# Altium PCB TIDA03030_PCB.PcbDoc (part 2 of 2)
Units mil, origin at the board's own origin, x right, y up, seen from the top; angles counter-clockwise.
Board outline 2230 x 2185 mil, 4 copper layers (Top Layer, Power, Gnd, Bottom Layer), stack 59.6 mil thick; 88 components, 48 nets, 250 pads, 119 vias.
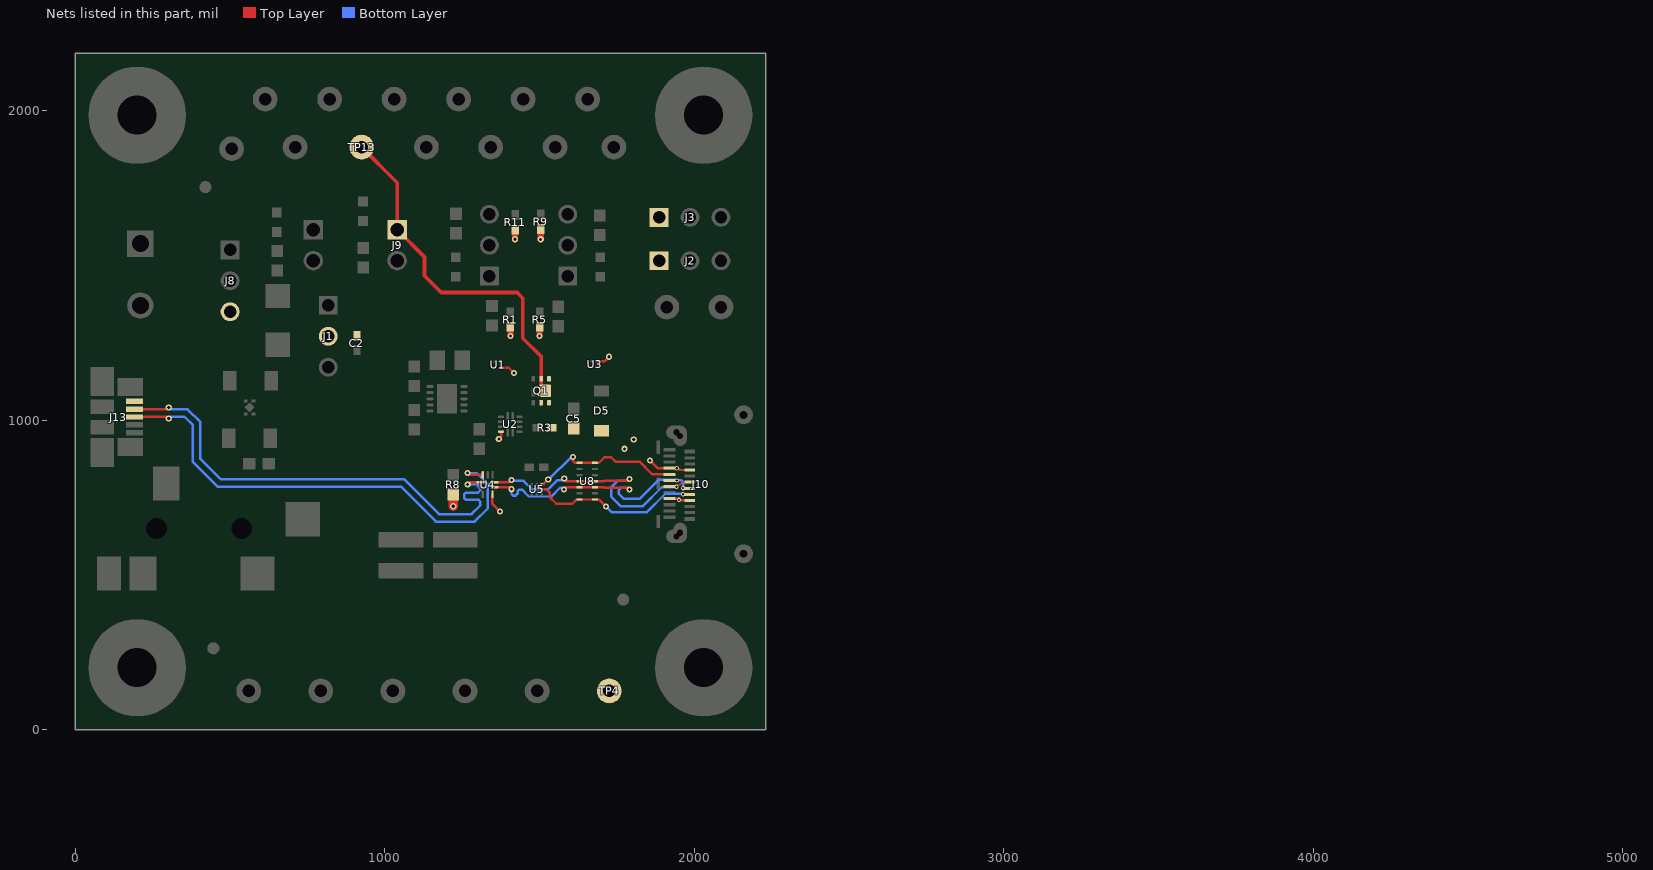
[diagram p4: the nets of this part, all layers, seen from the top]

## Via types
v1: diameter 20, hole 10, Top Layer to Bottom Layer, 108 vias
v2: diameter 14, hole 7, Top Layer to Bottom Layer, 7 vias
v3: diameter 19.68, hole 7.87, Top Layer to Bottom Layer, 4 vias

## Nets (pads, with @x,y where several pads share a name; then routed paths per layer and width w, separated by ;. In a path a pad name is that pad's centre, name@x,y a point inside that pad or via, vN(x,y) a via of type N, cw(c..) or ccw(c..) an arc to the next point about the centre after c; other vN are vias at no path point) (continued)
USB_C_D+: J10.A6 J10.B6 U4.7 U8.4 U8.11 | length 871.2
  Top Layer w6: v2(1942.44,784.84) 1948.75,791.16 1952.85,791.16 1961.09,799.4 J10.B6@1984.56,799.4
  Top Layer w8: U4.7@1355.62,799.44 1401.66,799.44 v1(1409.12,806.9) ; v1(1579.55,811.35) 1579.55,808.11 1585.09,802.57 U8.11@1629.39,802.57 U8.4@1678.61,802.57 1708.86,802.57 1711.02,804.72 1785.59,804.72 v1(1790.09,809.22)
  Bottom Layer w8: v1(1409.12,806.9) 1412.13,803.89 1448.23,803.89 1474.92,777.2 1528.19,777.2 1556.39,805.4 1573.61,805.4 v1(1579.55,811.35) ; v1(1790.09,809.22) 1785.59,804.72 1752.94,804.72 1731.07,782.85 1731.07,752.87 1762.74,721.2 1832.88,721.2 1894.65,782.98 1940.57,782.98 v2(1942.44,784.84)
USB_C_D-: J10.A7 J10.B7 U4.6 U8.3 U8.12 | length 813.1
  Top Layer w8: U4.6@1355.62,783.69 1402.41,783.69 v1(1409.22,776.88) ; v1(1578.92,775.46) 1578.92,777.02 1584.78,782.88 U8.12@1629.39,782.88 U8.3@1678.61,782.88 1708.43,782.88 1710.59,780.72 1785.59,780.72 v1(1790.09,776.22)
  Bottom Layer w8: v1(1409.22,776.88) 1409.22,760.95 1414.07,756.1 1422.74,756.1 1428.94,762.31 1428.94,771.05 1433.15,775.26 1442.93,775.26 1464.98,753.2 1538.13,753.2 1566.33,781.4 1572.98,781.4 v1(1578.92,775.46) ; v1(1790.09,776.22) 1785.59,780.72 1762.88,780.72 1755.07,772.91 1755.07,762.81 1772.68,745.2 1822.94,745.2 1884.71,806.98 1940.96,806.98 v2(1942.83,805.11) 1958.46,805.11 1964.12,799.45 1964.12,780.6 v2(1963.62,780.1)
USB_C_SBU1: J10.A8 U5.A3 U8.7 U8.8 | length 495.6
  Top Layer w8: U5.A3@1506.42,792.95 1513.11,792.95 v1(1528.03,807.87) ; v1(1607.7,881.21) 1607.7,868.62 1614.7,861.62 U8.8@1629.39,861.62 U8.7@1678.61,861.62 1691.19,861.62 1709.57,880.01 1731.25,880.01 1745.46,865.8 1822.35,865.8 1863.16,824.99 J10.A8@1919.6,824.99
  Bottom Layer w8: v1(1528.03,807.87) 1529.21,807.87 1602.55,881.21 v1(1607.7,881.21)
USB_C_SBU2: J10.B8 U5.B3 U8.1 U8.14 | length 532.9
  Top Layer w8: U5.B3@1506.42,777.2 1521.42,777.2 1532.38,766.24 1532.38,751.24 1553.73,729.89 1605.73,729.89 1619.35,743.51 U8.14@1629.39,743.51 U8.1@1678.61,743.51 1692.26,743.51 v1(1714.47,721.3)
  Bottom Layer w8: v1(1714.47,721.3) 1732.9,702.87 1846.78,702.87 1905.94,762.04 1961.55,762.04 v2(1963.24,760.34)
USB_C_VBUS: C5.1 D5.1 J9.1 J10.A4 J10.A9 J10.B4 J10.B9 Q1.1 Q1.2 Q1.5 Q1.6 Q1.8 R3.2 TP13.1 | length 1384.6
  Top Layer w8: v1@1856.56,869.41 1881.3,844.67 J10.A9@1919.6,844.67 1947.46,844.67 1953.37,838.77 J10.B4@1984.56,838.77 ; J10.A4@1919.6,746.25 1946.48,746.25 v2(1950.48,742.24) 1952.39,740.34 J10.B9@1984.56,740.34
  Top Layer w12: TP13.1@925,1882 1039.82,1767.18 J9.1@1039.82,1615 1128,1526.82 1128,1466 1182,1412 1427.64,1412 1445.63,1394.01 1445.63,1264.55 1505.78,1204.41 1505.78,1107.02 Q1.8@1517.8,1095
  other v1: 1856.52,869.41 1774.03,907.16 1804.2,937.14
  other v2: 1943.14,844.3
USB_D+: J13.3 U4.10 | length 1583.2
  Top Layer w8: J13.3@191.61,1010 222.78,1010 223.57,1010.8 295.88,1010.8 v1(301.88,1004.8) ; v1(1267.51,829.05) 1273.5,823.06 U4.10@1316.25,823.06
  Bottom Layer w8: v1(301.88,1004.8) 307.88,1010.8 352.68,1010.8 379.85,983.63 379.85,864.68 459.41,785.12 1052.06,785.12 1164.84,672.34 1290,672.34 1332.38,714.72 1332.38,793.63 1296.96,829.05 v1(1267.51,829.05)
USB_D-: J13.2 U4.1 | length 1583.1
  Top Layer w8: J13.2@191.61,1035.59 222.78,1035.59 223.57,1034.8 295.88,1034.8 v1(301.88,1040.8) ; v1(1267.64,792.08) 1275,799.44 U4.1@1310.35,799.44
  Bottom Layer w8: v1(301.88,1040.8) 307.88,1034.8 362.63,1034.8 403.85,993.57 403.85,874.63 469.35,809.12 1062,809.12 1174.78,696.34 1280.06,696.34 1308.38,724.66 1308.38,736.62 1303,742 1261.81,742 1256,747.81 1256,760.16 1261.84,766 1301,766 1308.38,773.38 1308.38,783.69 1299.99,792.08 v1(1267.64,792.08)
USB_VBUS: J8.3 J13.1
VDD: C2.1 J1.2 J2.1 J3.1 R1.1 R5.1 R8.1 R9.2 R11.2 TP4.1 U1.A2 U2.12 U3.A2 U4.5 | length 345.9
  Top Layer w8: U4.5@1347.75,760.07 1347.75,729.25 v1(1372,705) ; v1(1368.2,939.11) 1375.47,946.38 U2.12@1375.47,962.94 ; U1.A2@1374.84,1169.16 1400.3,1169.16 v1(1417.22,1152.24) ; U3.A2@1687.84,1190.84 1710.79,1190.84 v1(1724.56,1204.61)
  Top Layer w12: v1(1503.55,1584.02) v1@1504,1584.47
  Top Layer w20: v1(1405.5,1271.49) R1.1@1405.5,1301.38 ; v1(1421,1584.28) R11.2@1421,1615.38 ; v1(1500,1271.49) R5.1@1500,1301.38 ; v1@1504,1584.47 R9.2@1504,1617.38
  Top Layer w30: v1(1221,721.76) R8.1@1221,759.5
pads on no net: FID1.1 FID2.1 FID3.1 H1.1 H2.1 H3.1 H4.1 H7.0 H8.0 H9.0 H10.0 H11.0 H12.0 J10.A2 J10.A3 J10.A10 J10.A11 J10.B2 J10.B3 J10.B10 J10.B11 J12.5 J12.MH1 J12.MH2 J13.4 U2.1P U2.2P U2.7P U2.8P

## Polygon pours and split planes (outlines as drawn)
GND on Gnd "Power-No Net" (solid, pour order 23): 14,2161 27,2161 27,18 483,18 2209,18 2209,424 2209,2161 2099,2161
5V0 on Power "Power-No Net" (solid, pour order 13): 1806.26,2169.8 17.04,2169.8 17.04,1813.67 17.04,14.29 920.88,14.29 920.88,301.08 704.25,301.08 704.26,1020.77 626.31,1020.77 564.46,1020.77 564.46,1120.68 564.48,1184.93 564.48,1236.14 617.03,1236.14 761.2,1236.14 761.2,1283.62 761.2,1334.26 1011.14,1334.26 1011.14,1017.38 1062.81,1017.38 1132.53,1017.38 1132.53,1334.26 1397.1,1334.26 1397.11,1627.95 1806.26,1627.95
VDD on Power "Power-No Net" (solid, pour order 11): 775.46,1322.52 775.46,1323.1 1000.97,1323.1 1000.97,1031.92 1000.97,1008.96 1143.18,1008.96 1143.18,1322.52 1407.74,1322.52 1407.74,1423.09 1407.74,1616.34 1755.36,1616.34 1824.56,1616.34 1824.56,2169.63 2212.45,2169.63 2212.45,1575.23 2212.45,14.41 2108.07,14.41 1652.84,14.41 1652.84,149.76 1652.84,605.79 1194.86,605.78 1194.86,733.36 1562.45,733.36 1562.45,756.33 1562.45,984.71 1380.23,984.71 1380.23,897.12 876.99,897.12 876.99,1226.73 803.33,1226.73 775.17,1226.73 775.17,1318.05
3V3 on Power "Power-No Net" (solid, pour order 9): 864.86,886.97 864.86,1215.81 747.67,1215.81 580.74,1215.81 580.74,1038.03 593.59,1038.03 716.14,1038.03 716.14,827.77 716.14,314.93 937.8,314.93 937.8,14.36 1636.47,14.36 1636.47,105.65 1636.47,593.44 1521.27,593.44 1182.74,593.44 1182.74,744.93 1546.66,744.93 1546.66,973.51 1393.07,973.51 1393.07,886.97
GND on Bottom Layer "Power-No Net" (solid, pour order 7): 16.97,2154.82 16.98,2154.82 16.98,1726.07 16.98,16.53 1376.94,16.53 2210.03,16.53 2210.03,293.64 2210.03,2153.84 2050.3,2153.84

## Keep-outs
Keep-Out Layer:
  text "Keep - Out Layer" at -1418,-1898.49 h60

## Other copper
Top Layer:
  region net GND: 1990.59,686.27 1945.23,686.27 1937.42,694.08 1881.11,694.08 1878.38,696.81 1831.48,696.81 1819.8,685.13 1819.8,602.96 1898.1,524.66 2159.25,524.66 2182.11,547.52 2181.71,547.92 2181.71,582.08 2163.89,599.91 2056.54,599.91 2040.87,584.24 1989.18,584.24 1966.65,606.77 1966.65,649.17 1991.12,673.64 1991.12,685.75
  region net GND: 1590.09,1083.88 1630.73,1124.52 2157.88,1124.52 2193.98,1088.41 2193.98,1004.96 2172.41,983.39 2123.81,983.39 2076.56,1030.64 2026.58,1030.64 2001.94,1006 2001.94,892.91 1967.43,892.74 1961.45,898.72 1893.66,898.72 1889.99,895.06 1889.99,890.77 1888.13,888.9 1879.62,888.9 1876.42,892.1 1876.42,929.57 1767.63,1038.36 1729.97,1076.03 1656.26,1076.03 1629.89,1049.66 1629.89,1016.6 1590.09,1016.4
  region net USB_C_VBUS: 1724,984 1777.17,984 1819.97,941.2 1819.97,926.16 1787.2,893.39 1767.4,893.39 1718.07,942.72
  region net VDD: 1366.73,968.08 1364.51,965.86 1364.51,954.89 1353.66,944.04 1353.66,930.29 1358.07,925.88 1379.29,925.97 1385.36,932.04 1385.36,965.73 1383.02,968.08
  region net GND: 1497.56,860.04 1497.56,835.45 1485.72,823.61 1485.72,774.87 1487.96,772.63 1494.51,772.63 1495.7,773.82 1495.7,808.2 1523.41,835.91 1531.54,835.91 1531.54,859.96
  region net 5V0: 569.9,1025.02 665.19,1025.02 697.82,992.39 697.82,845.92 677.89,825.99 613.44,825.99 613.44,826.08 604.78,834.74 604.78,906.33 607.61,909.17 607.61,967.74 570.08,1005.26 570.08,1010.88
  region net VDD: 783.95,1295.03 783.95,1244.03 792.65,1235.33 872.87,1235.33 893.83,1256.28 932.97,1256.28 941.68,1265 941.16,1265.53 941.16,1297.56 931.18,1307.54 796.38,1307.54
  region net USB_VBUS: 523.74,1383.68 460.58,1383.68 446.89,1369.98 446.89,1289.97 227.62,1070.7 165.28,1070.7 163.6,1069.03 163.6,1052.56 164.96,1051.2 166.8,1051.2 279.22,1051.2 297.52,1069.49 325.48,1069.49 539.1,1283.11 539.11,1369.44
  region net GND: 48.12,1202.5 30,1220.62 30,1558 85,1613 267,1613 282,1598 282,1542 267,1527 142,1527 114,1499 114,1284 150,1248 214,1248 226.61,1235.39 226.61,1197.73
  region net GND: 1075,1258 1093,1276 1182,1276 1196,1262 1196,1159 1235,1120 1235,967 1159.93,891.93 1067.97,891.93 1056.45,903.45 1056.45,977.83 1068.63,990.1 1074,990.14 1136.14,990.14 1168,1022 1168,1132 1148,1152 1077,1152 1075,1154
  region net NetJ6_1: 1440.68,1106 1310.44,1106 1278.44,1074 1246,1074 1243,1071 1243,1024 1248,1019 1288.43,1019 1337.71,1068.28 1450.41,1068.28 1473.69,1045 1483,1045 1487,1049 1487,1103 1484,1106
  region net NetR1_2: 1327.15,1388.66 1411.03,1388.66 1424.86,1374.84 1424.86,1338.46 1419.26,1332.87 1390.86,1332.87 1375.36,1348.37 1327.04,1348.37 1324.56,1350.85 1324.56,1386.09
  region net NetR5_2: 1540.6,1388.5 1581.68,1388.5 1588.05,1382.12 1588.05,1351.75 1582.86,1346.56 1527.8,1346.56 1514.14,1332.9 1485.54,1332.9 1482.15,1336.29 1482.15,1376.24 1494.07,1388.17
  region net 3V3: 569.9,1057.22 569.83,1086.22 576.36,1092.73 611.23,1092.73 611.23,1158.23 617.27,1164.27 677.73,1164.27 686.08,1155.92 686.08,1084.08 659.22,1057.22
  region net NetJ7_2: 148.32,1419.24 289.24,1419.24 457.34,1587.34 539.72,1587.34 546.03,1581.03 546.03,1520.03 533.17,1507.17 481.17,1507.17 285.21,1311.21 148.32,1311.21
  region net GND: 48.04,1171.27 48.04,798.11 70.83,775.32 195.73,775.32 219.46,799.05 219.46,942.67 219.49,967.96 218.53,968.92 164.53,968.92 162.56,966.95 162.56,948.28 156.24,941.96 126.36,941.96 124.57,943.76 124.57,1069.57 132.82,1077.82 222.88,1077.82 226.61,1081.54 226.61,1197.73 207.05,1217.29 62.95,1217.29 48.12,1202.5
  region net USB_C_VBUS: 1498.83,1148.9 1498.83,1041.17 1523.87,1016.13 1523.87,957.13 1547.22,933.78 1727,933.78 1727,981 1724,984 1638,984 1629,993 1588,993 1569,1012 1569,1144.18 1561.18,1152 1501.93,1152
  region net GND: 566.86,1283 553.94,1270.07 553.94,1214.13 564.06,1204 754.42,1204 754.42,1283
  region net 5V0: 475,1410 539,1410 588,1361 758,1361 779,1340 852,1340 860,1348 860,1422 832,1450 826,1450 601,1450 560,1491 481,1491 463,1473 463,1422
  region net 5V0: 1156,1075 1137,1075 1115,1053 1018.06,1053 1011.14,1046.08 1011.14,1018.42 1016.57,1013 1144,1013 1158,1027 1158,1073
  region net GND: 578.87,1041.26 578.4,1040.78 531.51,1040.78 517.96,1027.24 517.96,909.35 510.88,902.27 470.59,902.27 463.24,909.62 463.24,1154.01 473.52,1164.29 517.23,1164.29 523.6,1157.93 523.6,1092.74 557.22,1092.74 563.07,1086.88 563.07,1041.27
  text "TOP Layer" at -1415,-1905 h60
Gnd:
  text "GND" at -1405,-1905 h60
Power:
  text "POWER" at -1458,-1908 h60
Bottom Layer:
  region net USB_C_VBUS: 1753.5,937.78 1753.5,896.06 1765.9,883.66 1822.45,883.66 1869.6,836.51 1950.27,836.51 1957.27,843.51 1970.85,843.51 1978.83,835.53 1978.83,751.22 1970.94,743.33 1962.78,743.33 1956.55,749.56 1936.15,749.56 1933.51,746.92 1933.51,726.94 1938.27,722.18 1990.78,722.18 2002.16,733.56 2002.15,874.53 1986.11,890.57 1888.21,890.57 1824.9,953.89 1769.61,953.89
  text "BOTTOM Layer" at -1395,-1905 h60

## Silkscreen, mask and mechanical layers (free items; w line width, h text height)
Top Overlay:
  text "TOP Overlay" at -1418,-1898.49 h60
Bottom Overlay:
  text "Bottom Overlay" at -1418,-1898.49 h60
Top Paste:
  text "Top Paste" at -1418,-1898.49 h60
Bottom Paste:
  text "Bottom Paste" at -1418,-1898.49 h60
Top Solder:
  text "Top Solder" at -1418,-1898.49 h60
Bottom Solder:
  text "Bottom Solder" at -1418,-1898.49 h60
Drill Guide:
  text "Drill guide" at -1418,-1898.49 h60
M1 Board Outline:
  lines w3.94: 2215.86,613.37 2230,613.37 2230,601.28 2230.03,601.28 2230.03,0 ; 2215.86,971.64 2230,971.64 ; 2230,0 0,0 0,2185 2230,2185 2230,971.64 ; 2230,971.64 2230,971.64
  text "M1 Board Outline" at -1418,-1898.49 h60
M2 Board Dimensions:
  rectangle: -725,-405 -600,-280
  rectangle: -600,-530 -225,-405
  lines w7: -725,-405 275,-405 ; -600,-530 -600,-280 ; -475,-530 -475,-280 ; -225,-530 -225,-280 ; 25,-530 25,-280 ; -725,-530 275,-530 275,-280 -725,-280 -725,-530
  lines w10: 1061.09,1146.84 1061.16,1213.95 ; 1061.15,938.26 1061.15,999.16 ; 1061.23,743.01 1061.23,696 1102.27,696 ; 1061.23,810.7 1061.23,841.06 ; 1061.23,1046.91 1061.23,1084.58 ; 1109.79,1228 1149.72,1228 ; 1202.93,696 1242.49,696 ; 1230.57,1228 1269.48,1228 ; 1289.04,696 1326.39,696 ; 1342.75,1228 1398.25,1228 ; 1449.93,1228 1473.11,1228 ; 1521.39,1228 1560.18,1228 ; 1606.96,1228 1632.23,1228 ; 1650.45,696 1695.04,696 ; 1687.26,1228 1708.79,1228 ; 1756.48,696 1786,696 1786,721.24 ; 1757.12,1228 1786,1228 1786,1199.38 ; 1786,860.92 1786,896.91 ; 1786,972.04 1786,1019.46
  text "M2 Board Dimension" at -1418,-1898.49 h60
M3 3D STEP Top:
  text ".Layer_Name" at -1418,-1898.49 h60
M4 3D STEP Bottom:
  text ".Layer_Name" at -1418,-1898.49 h60
M5 Assembly Top:
  lines w10: -2287,-1970.17 4313,-1970.17 ; -2287,-1766.83 4315,-1766.83 ; -2287,-1563.5 -2287,-2173.5 1718,-2173.5 4315,-2173.5 4315,-1563.5 -2286.5,-1563.5 -2286.5,-2173.5 -711,-2173.5 ; 178,-2173.5 178,-1563.5 ; 1445,-1766.83 1445,-1563.5 ; 2285,-1766.83 2285,-1563.5 ; 2907,-2180 2907,-1977.17
  text "COMPONENTS MARKED 'DNP' SHOULD NOT BE POPULATED." at -841.5,-1358.5 h60
  text "ASSEMBLY VARIANT:" at -842,-1474 h60
  text ".VariantName" at 194,-1474 h60
  text "PCB VIEWED FROM TOP SIDE" at -2223.5,-1695.67 h60
  text "BOARD #:" at 253,-1695.67 h60
  text ".PRJ_Number" at 798.5,-1695.67 h60
  text "REV:" at 1643,-1695.67 h60
  text ".PCB_Rev" at 1934.5,-1695.67 h60
  text "SVN REV:" at 2481,-1695.67 h60
  text ".VersionControl_RevNumber" at 2987,-1695.67 h60
  text "TID #:" at 253,-1899 h60
  text ".TID" at 798.5,-1899 h60
  text "PLOT NAME =" at -2223.5,-2104.34 h60
  text ".plot_File_Name" at -1418,-2104.34 h60
  text "GENERATED    :" at 255,-2104.34 h60
  text ".Print_Date" at 1124.5,-2104.34 h60
  text ".Print_Time" at 1853.5,-2104.34 h60
  text "TEXAS INSTRUMENTS" at 3118,-2104.34 h60
M6 Assembly Bottom:
  lines w10: -2287.5,-1767.33 4314.5,-1767.33 ; -2285.5,-1970.67 4314.5,-1970.67 ; -879.5,-2180.5 -879.5,-1977.67 ; -257.5,-1767.33 -257.5,-1564 ; 582.5,-1767.33 582.5,-1564 ; 1849.5,-2174 1849.5,-1564 ; 2738.5,-2174 4314,-2174 4314,-1564 -2287.5,-1564 -2287.5,-2174 309.5,-2174 4314.5,-2174 4314.5,-1564
  text "COMPONENTS MARKED 'DNP' SHOULD NOT BE POPULATED." at 4107,-1358 h60
  text ".VariantName" at 3063,-1474 h60
  text "ASSEMBLY VARIANT:" at 4102,-1474 h60
  text ".VersionControl_RevNumber" at -959.5,-1696.17 h60
  text "SVN REV:" at -453.5,-1696.17 h60
  text ".PCB_Rev" at 93,-1696.17 h60
  text "REV:" at 384.5,-1696.17 h60
  text ".PRJ_Number" at 1229,-1696.17 h60
  text "BOARD #:" at 1774.5,-1696.17 h60
  text "PCB VIEWED FROM BOTTOM SIDE" at 4251,-1696.17 h60
  text ".TID" at 1229,-1899.5 h60
  text "TID #:" at 1774.5,-1899.5 h60
  text "TEXAS INSTRUMENTS" at -1090.5,-2104.84 h60
  text ".Print_Time" at 174,-2104.84 h60
  text ".Print_Date" at 903,-2104.84 h60
  text "GENERATED    :" at 1772.5,-2104.84 h60
  text ".plot_File_Name" at 3445.5,-2104.84 h60
  text "PLOT NAME =" at 4251,-2104.84 h60
M9 Title Sheet:
  drawing of 57 lines, arcs and shapes, not listed
  text "1" at -1255.16,6996.5 h70
  text "2" at 1240.5,6996.5 h70
  text "3" at 3729.84,6996.5 h70
  text "4" at 6236.51,6996.5 h70
  text "5" at 8735.5,6996.5 h70
  text "6" at 11240.5,6996.5 h70
  text "A" at -2411.5,5853.5 h70
  text "A" at 12388.5,5853.5 h70
  text "B" at -2411.5,3473.5 h70
  text "B" at 12388.5,3473.5 h70
  text "C" at -2411.5,1098.5 h70
  text "C" at 12388.5,1098.5 h70
  text "PROJECT TITLE:" at 9348.5,-762.5 h45
  text "TIDA03030" at 9398.5,-895.83 h70
  text "DESIGNED FOR:" at 9348.5,-1063.5 h45
  text "TI_TIDA03030" at 9398.5,-1203.5 h70
  text "D" at -2411.5,-1271.5 h70
  text "D" at 12388.5,-1271.5 h70
  text "FILE NAME:" at 9348.5,-1363.5 h45
  text "TIDA03030_PCB_PcbDoc" at 9398.5,-1483.5 h70
  text "Texas Instruments (TI) and/or its licensors do not warrant the accuracy or completeness of this specification" at 4379,-1645.34 h45
  text "ENGINEER:" at 9348.5,-1653.5 h45
  text "LAYOUT BY:" at 10853.5,-1653.5 h45
  text "or any information contained therein. TI and/or its licensors do not warrant that this design will meet" at 4334.01,-1758 h45
  text "ANDY" at 9398.5,-1808.49 h70
  text "PACTRONINC" at 10904,-1808.49 h70
  text "the specifications, will be suitable for your application or fit for any particular purpose, or will operate in" at 4334.01,-1870.67 h45
  text "M9  Title Sheet" at -1418,-1898.49 h60
  text "ALTIUM DESIGNER VERSION:" at 10853.5,-1963.5 h45
  text "an implementation. TI and/or its licensors do not warrant that the design is production worthy. You should" at 4334.01,-1983.33 h45
  text "completely validate and test your design implementation to confirm the system functionality for your application." at 4379,-2096 h45
  text "Scale : 1.00" at 9398.5,-2096.83 h70
  text "14.3.14.34663" at 10904,-2096.83 h70
  text "1" at -1255.16,-2303.5 h70
  text "2" at 1240.5,-2303.5 h70
  text "3" at 3729.84,-2303.5 h70
  text "4" at 6236.51,-2303.5 h70
  text "5" at 8735.5,-2303.5 h70
  text "6" at 11240.5,-2303.5 h70
M10 Fab Notes:
  drawing of 173 lines, arcs and shapes, not listed
  text "DESIGN INFORMATION" at 10383.02,5161 h60
  text "MIN. TRACK WIDTH:" at 9738.46,4981 h60
  text "6" at 10834.7,4981 h60
  text "MIL" at 10989.46,4981 h60
  text "5" at 10835,4850 h60
  text "MIN. CLEARANCE:" at 9738.46,4849 h60
  text "MIL" at 10989.46,4849 h60
  text "MIN. VIA PAD SIZE:" at 9738.46,4717 h60
  text "14" at 10804.71,4717 h60
  text "MIL" at 10989.46,4717 h60
  text "0.05mm (2MIL)" at 10433.46,4575.29 h60
  text "MINIMUM ANNULAR RING" at 9409.23,4571 h60
  text "EXTERNAL" at 11141.46,4571 h60
  text "PER" at 9609.23,4453 h60
  text "IPC-D-275 CLASS 2 LEVEL C" at 9829.23,4453 h60
  text "MIL, HOLES" at 11317.46,4340.71 h60
  text "+/-" at 10925,4340 h60
  text "+/-" at 11779,4340 h60
  text "REGISTRATION TOLERANCES:" at 9409.23,4335 h60
  text "METAL" at 10609,4335 h60
  text "5" at 11185.2,4335 h60
  text "3" at 12018.2,4335 h60
  text "MIL" at 12134.46,4335 h60
  text "+/-" at 11779,4222 h60
  text "HOLE SIZE TOLERANCE (UNLESS OTHERWISE SPECIFIED):" at 9409.23,4217 h60
  text "3" at 12018.2,4217 h60
  text "MIL" at 12134.46,4217 h60
  text "MATERIAL:" at 9334.46,4007.54 h60
  text "FR-4 High Tg" at 10320.9,3867.21 h60
  text "FR-408" at 9755.46,3858.64 h60
  text "OTHER" at 11243.46,3858.64 h60
  text "X" at 10166,3855 h60
  text "62MIL (1.6mm) +/-10%" at 10075.56,3695.92 h60
  text "THICKNESS:" at 9409.23,3691.64 h60
  text "X" at 9947.4,3691.64 h60
  text "OTHER" at 11360.46,3691.64 h60
  text "TOLERANCE:" at 9409.23,3533.64 h60
  text "X" at 10248.53,3533.64 h60
  text "ANSI IPC-6012 TYPE 3 CLASS 2" at 10435.48,3533.64 h60
  text "OTHER +/-" at 10435.46,3377.64 h60
  text "BOW & TWIST:" at 9409.23,3220.64 h60
  text "X" at 10248.53,3220.64 h60
  text "ANSI IPC-6012 TYPE 3 CLASS 2" at 10435.48,3220.64 h60
  text "OTHER +/-" at 10435.46,3062.13 h60
  text "DRILLING:" at 9334.46,2923.64 h60
  text "REFERENCE:" at 9409.23,2806.64 h60
  text "X" at 10057.46,2806.64 h60
  text "AS SHOWN" at 10244.46,2806.64 h60
  text "X" at 10958.46,2806.64 h60
  text "NC_DRILL FILES" at 11095.46,2806.64 h60
  text "PTH COPPER THICKNESS:" at 9409.23,2648.64 h60
  text "X" at 10539.46,2648.64 h60
  text "20-30 um" at 10676.46,2648.64 h60
  text "OTHER" at 11393.46,2648.64 h60
  text "BOARD FINISH:" at 9334.46,2489.64 h60
  text "SILKSCREEN:" at 9489.68,2371.64 h60
  text "X" at 10438.46,2371.64 h60
  text "TOP" at 10564.46,2371.64 h60
  text "X" at 10948.46,2371.64 h60
  text "BOTTOM" at 11075.46,2371.64 h60
  text "SILKSCREEN COLOR:" at 9489.68,2204.64 h60
  text "X" at 10437.42,2204.64 h60
  text "WHITE" at 10564.46,2204.64 h60
  text "OTHER" at 11075.46,2204.64 h60
  text "X" at 10568.42,2045.44 h60
  text "GREEN" at 10695.46,2045.44 h60
  text "OTHER" at 11313.46,2045.44 h60
  text "SOLDER RESIST COLOR:" at 9489.68,2034.64 h60
  text "MATTE" at 10695.46,1875.44 h60
  text "SEMI-GLOSS" at 11313,1874.8 h60
  text "IMMERSION GOLD (ENIG)" at 10395.46,1686.92 h60
  text "ENEPIG" at 11733,1683.64 h60
  text "SURFACE FINISH:" at 9334.46,1682.64 h60
  text "X" at 10208.51,1682.64 h60
  text "IMM. TIN/SILVER OR EQUIV" at 9664,1525.64 h60
  text "OTHER" at 11095.46,1525.64 h60
  text "ARRAY/PANEL:" at 9334.46,1346.64 h60
  text "CUT AND TRIM PER M1 BOARD OUTLINE" at 10395.46,1342.35 h60
  text "N.C. ROUTE" at 10395.46,1190.64 h60
  text "V. SCORE" at 11261.46,1190.64 h60
  text "CERTIFICATION:" at 9334.46,1053.64 h60
  text "MATERIALS AND WORKMANSHIP FOR ALL PCBS" at 10059.46,1053.64 h60
  text "TO MEET OR EXCEED THE REQUIREMENTS OF:" at 10059.46,955.64 h60
  text "X" at 9685.96,819.13 h60
  text "ANSI IPC-A-600F CLASS ->" at 9824.96,819.13 h60
  text "X" at 11464.02,819.13 h60
  text "2" at 11582.96,819.14 h60
  text "1" at 11267.96,817.64 h60
  text "3" at 11936.96,817.64 h60
  text "X" at 10500.02,659.64 h60
  text "RoHS" at 10636.96,659.64 h60
  text "OTHER" at 11281.36,659.64 h60
  text "PER ORDER" at 11678.42,659.64 h60
  text "Note:" at 2949.6,582.97 h100
  text "ALL BOARDS MUST MEET OR EXCEED UL94-V0 REQUIREMENTS." at 9362,494 h60
  text "All 8 mil traces with 16mil air gap on  top and bottom  layer need to be controlled impedance of 100ohms" at 2944.31,440.43 h100
  text "PCB MUST BEAR THE UL94V-0 UL REGISTERED MATERIAL ID NUMBER" at 9362,374 h60
  text "ADDITIONAL REQUIREMENTS:" at 9334.46,200.64 h60
  text "MICROSECTION:" at 9409.23,85.64 h60
  text "YES" at 10314.96,85.64 h60
  text "REQUIRED" at 11176.46,-70.51 h60
  text "BARE BOARD ELEC. TEST:" at 9409.23,-73.36 h60
  text "NONE" at 10714.96,-73.36 h60
  text "X" at 11049.46,-73.36 h60
  text "PER ORDER" at 11768.46,-73.36 h60
  text "M10 Fab Notes" at -1418,-1898.49 h60
M11 Gerber Information:
  lines w10: -2287,-1970.17 4313,-1970.17 ; -2287,-1766.83 4315,-1766.83 ; -2287,-1563.5 -2287,-2173.5 1718,-2173.5 4315,-2173.5 4315,-1563.5 -2286.5,-1563.5 -2286.5,-2173.5 -711,-2173.5 ; 178,-2173.5 178,-1563.5 ; 1445,-1766.83 1445,-1563.5 ; 2285,-1766.83 2285,-1563.5 ; 2907,-2180 2907,-1977.17
  text "ALL ARTWORK VIEWED FROM TOP SIDE" at -2223.5,-1695.67 h60
  text "BOARD #:" at 253,-1695.67 h60
  text ".PRJ_Number" at 798.5,-1695.67 h60
  text "REV:" at 1643,-1695.67 h60
  text ".PCB_Rev" at 1934.5,-1695.67 h60
  text "SVN REV:" at 2481,-1695.67 h60
  text ".VersionControl_RevNumber" at 2987,-1695.67 h60
  text "LAYER NAME =" at -2223.5,-1898.49 h60
  text "TID #:" at 253,-1899 h60
  text ".TID" at 798.5,-1899 h60
  text "PLOT NAME =" at -2223.5,-2104.34 h60
  text ".plot_File_Name" at -1418,-2104.34 h60
  text "GENERATED    :" at 255,-2104.34 h60
  text ".Print_Date" at 1124.5,-2104.34 h60
  text ".Print_Time" at 1853.5,-2104.34 h60
  text "TEXAS INSTRUMENTS" at 3118,-2104.34 h60
M12 Stackup:
  drawing of 295 lines, arcs and shapes, not listed
  text "Layer" at 3034.58,4645 h60
  text "Name" at 3444.49,4645 h60
  text "Material" at 4374.23,4645 h60
  text "Thickness" at 5234,4645 h60
  text "Constant" at 5883.84,4645 h60
  text "Board Layer Stack" at 6453.7,4645 h60
  text "1" at 3034.58,4525 h60
  text "Top Overlay" at 3444.49,4525 h60
  text "2" at 3034.58,4405 h60
  text "Top Solder" at 3444.49,4405 h60
  text "Solder Resist" at 4374.23,4405 h60
  text "0.70mil" at 5234,4405 h60
  text "3.5" at 5883.84,4405 h60
  text "3" at 3034.58,4285 h60
  text "Top Layer" at 3444.49,4285 h60
  text "Copper" at 4374.23,4285 h60
  text "1.50mil" at 5234,4285 h60
  text "4" at 3034.58,4165 h60
  text "Dielectric1" at 3444.49,4165 h60
  text "FR-4" at 4374.23,4165 h60
  text "6.00mil" at 5234,4165 h60
  text "4.8" at 5883.84,4165 h60
  text "5" at 3034.58,4045 h60
  text "Power" at 3444.49,4045 h60
  text "Copper" at 4374.23,4045 h60
  text "1.30mil" at 5234,4045 h60
  text "6" at 3034.58,3925 h60
  text "Dielectric 2" at 3444.49,3925 h60
  text "42.00mil" at 5234,3925 h60
  text "4.2" at 5883.84,3925 h60
  text "7" at 3034.58,3805 h60
  text "Gnd" at 3444.49,3805 h60
  text "Copper" at 4374.23,3805 h60
  text "1.30mil" at 5234,3805 h60
  text "8" at 3034.58,3685 h60
  text "Dielectric 3" at 3444.49,3685 h60
  text "6.00mil" at 5234,3685 h60
  text "4.2" at 5883.84,3685 h60
  text "9" at 3034.58,3565 h60
  text "Bottom Layer" at 3444.49,3565 h60
  text "Copper" at 4374.23,3565 h60
  text "1.50mil" at 5234,3565 h60
  text "10" at 3034.58,3445 h60
  text "Bottom Solder" at 3444.49,3445 h60
  text "Solder Resist" at 4374.23,3445 h60
  text "0.70mil" at 5234,3445 h60
  text "3.5" at 5883.84,3445 h60
  text "11" at 3034.58,3325 h60
  text "Bottom Overlay" at 3444.49,3325 h60
  text "M12 Stack Up" at -1418,-1898.49 h60
M13 Component Bodies Top:
  text ".Layer_Name" at -1418,-1898.49 h60
M14 Component Bodies Bottom:
  text ".Layer_Name" at -1418,-1898.49 h60
M15 Courtyards Top:
  text ".Layer_Name" at -1418,-1898.49 h60
M16 Courtyards Bottom:
  text ".Layer_Name" at -1418,-1898.49 h60
Drill Drawing:
  lines w10: 3038.12,2790.94 3071.46,2807.61 3104.79,2790.94 3088.12,2824.27 3104.79,2857.61 3071.46,2840.94 3038.12,2857.61 3054.79,2824.27 3038.12,2790.94 ; 3038.12,2940.94 3038.12,2957.61 3054.79,2974.27 3038.12,2990.94 3038.12,3007.61 3054.79,3007.61 3071.46,2990.94 3088.12,3007.61 3104.79,3007.61 3104.79,2990.94 3088.12,2974.27 3104.79,2957.61 3104.79,2940.94 3088.12,2940.94 3071.46,2957.61 3054.79,2940.94 3038.12,2940.94 ; 3038.12,3107.61 3054.79,3107.61 3054.79,3090.94 3088.12,3090.94 3088.12,3107.61 3104.79,3107.61 3104.79,3140.94 3088.12,3140.94 3088.12,3157.61 3054.79,3157.61 3054.79,3140.94 3038.12,3140.94 3038.12,3107.61 ; 3051.46,2804.27 3071.46,2814.27 3091.46,2804.27 3081.46,2824.27 3091.46,2844.27 3071.46,2834.27 3051.46,2844.27 3061.46,2824.27 3051.46,2804.27 ; 3051.46,2954.27 3051.46,2964.27 3061.46,2974.27 3051.46,2984.27 3051.46,2994.27 3061.46,2994.27 3071.46,2984.27 3081.46,2994.27 3091.46,2994.27 3091.46,2984.27 3081.46,2974.27 3091.46,2964.27 3091.46,2954.27 3081.46,2954.27 3071.46,2964.27 3061.46,2954.27 3051.46,2954.27 ; 3051.46,3114.27 3061.46,3114.27 3061.46,3104.27 3081.46,3104.27 3081.46,3114.27 3091.46,3114.27 3091.46,3134.27 3081.46,3134.27 3081.46,3144.27 3061.46,3144.27 3061.46,3134.27 3051.46,3134.27 3051.46,3114.27
  lines w15: 2978.33,1395.94 9212.62,1395.94 ; 2978.33,3195.94 9212.62,3195.94 ; 3529.21,1245.94 3529.21,3345.94 ; 4227.02,1245.94 4227.02,3345.94 ; 5572.62,1245.94 5572.62,3345.94 ; 6078.5,1245.94 6078.5,3345.94 ; 6812.3,1245.94 6812.3,3345.94 ; 7953.97,1245.94 7953.97,3345.94 ; 2978.33,1245.94 9212.62,1245.94 9212.62,3345.94 2978.33,3345.94 2978.33,1245.94
  text "Symbol" at 3068.33,3240.94 h72
  text "Hit Count" at 3574.21,3240.94 h72
  text "Finished Hole Size" at 4272.02,3240.94 h72
  text "Plated" at 5617.62,3240.94 h72
  text "Hole Type" at 6123.5,3240.94 h72
  text "Physical Length" at 6857.3,3240.94 h72
  text "Rout Path Length" at 7998.97,3240.94 h72
  text "2" at 3574.21,3090.94 h60
  text "19.69mil (0.500mm)" at 4272.02,3090.94 h60
  text "PTH" at 5617.62,3090.94 h60
  text "Slot" at 6123.5,3090.94 h60
  text "43.11mil (1.095mm)" at 6857.3,3090.94 h60
  text "23.43mil (0.595mm)" at 7998.97,3090.94 h60
  text "2" at 3574.21,2940.94 h60
  text "19.69mil (0.500mm)" at 4272.02,2940.94 h60
  text "PTH" at 5617.62,2940.94 h60
  text "Slot" at 6123.5,2940.94 h60
  text "43.31mil (1.100mm)" at 6857.3,2940.94 h60
  text "23.62mil (0.600mm)" at 7998.97,2940.94 h60
  text "2" at 3574.21,2790.94 h60
  text "25.59mil (0.650mm)" at 4272.02,2790.94 h60
  text "PTH" at 5617.62,2790.94 h60
  text "Round" at 6123.5,2790.94 h60
  text "-" at 6857.3,2790.94 h60
  text "-" at 7998.97,2790.94 h60
  text "2" at 3574.21,2640.94 h60
  text "55.12mil (1.400mm)" at 4272.02,2640.94 h60
  text "PTH" at 5617.62,2640.94 h60
  text "Round" at 6123.5,2640.94 h60
  text "-" at 6857.3,2640.94 h60
  text "-" at 7998.97,2640.94 h60
  text "E" at 3039.24,2630.95 h66.67
  text "2" at 3574.21,2490.94 h60
  text "66.93mil (1.700mm)" at 4272.02,2490.94 h60
  text "NPTH" at 5617.62,2490.94 h60
  text "Round" at 6123.5,2490.94 h60
  text "-" at 6857.3,2490.94 h60
  text "-" at 7998.97,2490.94 h60
  text "D" at 3039.24,2480.95 h66.67
  text "4" at 3574.21,2340.94 h60
  text "7.87mil (0.200mm)" at 4272.02,2340.94 h60
  text "PTH" at 5617.62,2340.94 h60
  text "Round" at 6123.5,2340.94 h60
  text "-" at 6857.3,2340.94 h60
  text "-" at 7998.97,2340.94 h60
  text "I" at 3050.35,2330.95 h66.67
  text "4" at 3574.21,2190.94 h60
  text "43.31mil (1.100mm)" at 4272.02,2190.94 h60
  text "PTH" at 5617.62,2190.94 h60
  text "Round" at 6123.5,2190.94 h60
  text "-" at 6857.3,2190.94 h60
  text "-" at 7998.97,2190.94 h60
  text "F" at 3039.24,2180.95 h66.67
  text "4" at 3574.21,2040.94 h60
  text "125.98mil (3.200mm)" at 4272.02,2040.94 h60
  text "PTH" at 5617.62,2040.94 h60
  text "Round" at 6123.5,2040.94 h60
  text "-" at 6857.3,2040.94 h60
  text "-" at 7998.97,2040.94 h60
  text "C" at 3039.24,2030.95 h66.67
  text "7" at 3574.21,1890.94 h60
  text "7.00mil (0.178mm)" at 4272.02,1890.94 h60
  text "PTH" at 5617.62,1890.94 h60
  text "Round" at 6123.5,1890.94 h60
  text "-" at 6857.3,1890.94 h60
  text "-" at 7998.97,1890.94 h60
  text "H" at 3039.24,1880.95 h66.67
  text "18" at 3574.21,1740.94 h60
  text "40.16mil (1.020mm)" at 4272.02,1740.94 h60
  text "PTH" at 5617.62,1740.94 h60
  text "Round" at 6123.5,1740.94 h60
  text "-" at 6857.3,1740.94 h60
  text "-" at 7998.97,1740.94 h60
  text "B" at 3039.24,1730.95 h66.67
  text "21" at 3574.21,1590.94 h60
  text "40.00mil (1.016mm)" at 4272.02,1590.94 h60
  text "PTH" at 5617.62,1590.94 h60
  text "Round" at 6123.5,1590.94 h60
  text "-" at 6857.3,1590.94 h60
  text "-" at 7998.97,1590.94 h60
  text "A" at 3039.24,1580.95 h66.67
  text "108" at 3574.21,1440.94 h60
  text "10.00mil (0.254mm)" at 4272.02,1440.94 h60
  text "PTH" at 5617.62,1440.94 h60
  text "Round" at 6123.5,1440.94 h60
  text "-" at 6857.3,1440.94 h60
  text "-" at 7998.97,1440.94 h60
  text "G" at 3039.24,1430.95 h66.67
  text "176 Total" at 3574.21,1290.94 h60
  text "Slot definitions :" at 3068.33,1145.97 h60
  text "Rout Path Length" at 4101.02,1145.97 h60
  text "= Calculated from tool start centre position to tool end centre position." at 5083.73,1145.97 h60
  text "Physical Length" at 4101.02,1045.99 h60
  text "= Rout Path Length + Tool Size = Slot length as defined in the PCB layout" at 5023.75,1045.99 h60
  text "Drill Drawing" at -1470,-1905 h60
M17 Embedded Cavity:
  text ".Layer_Name" at -1418,-1898.49 h60
M18 Embedded Assembly:
  text ".Layer_Name" at -1418,-1898.49 h60
M19 Embedded Keepout:
  text ".Layer_Name" at -1418,-1898.49 h60

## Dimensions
-45,697 to -43,1229 on M2 Board Dimensions
1063,2183 to 1788,2184 on M2 Board Dimensions
-725,-530 to 275,-530 on M2 Board Dimensions
2230,2185 to 2230,0 on M2 Board Dimensions
0,-10 to 2230,-10 on M2 Board Dimensions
